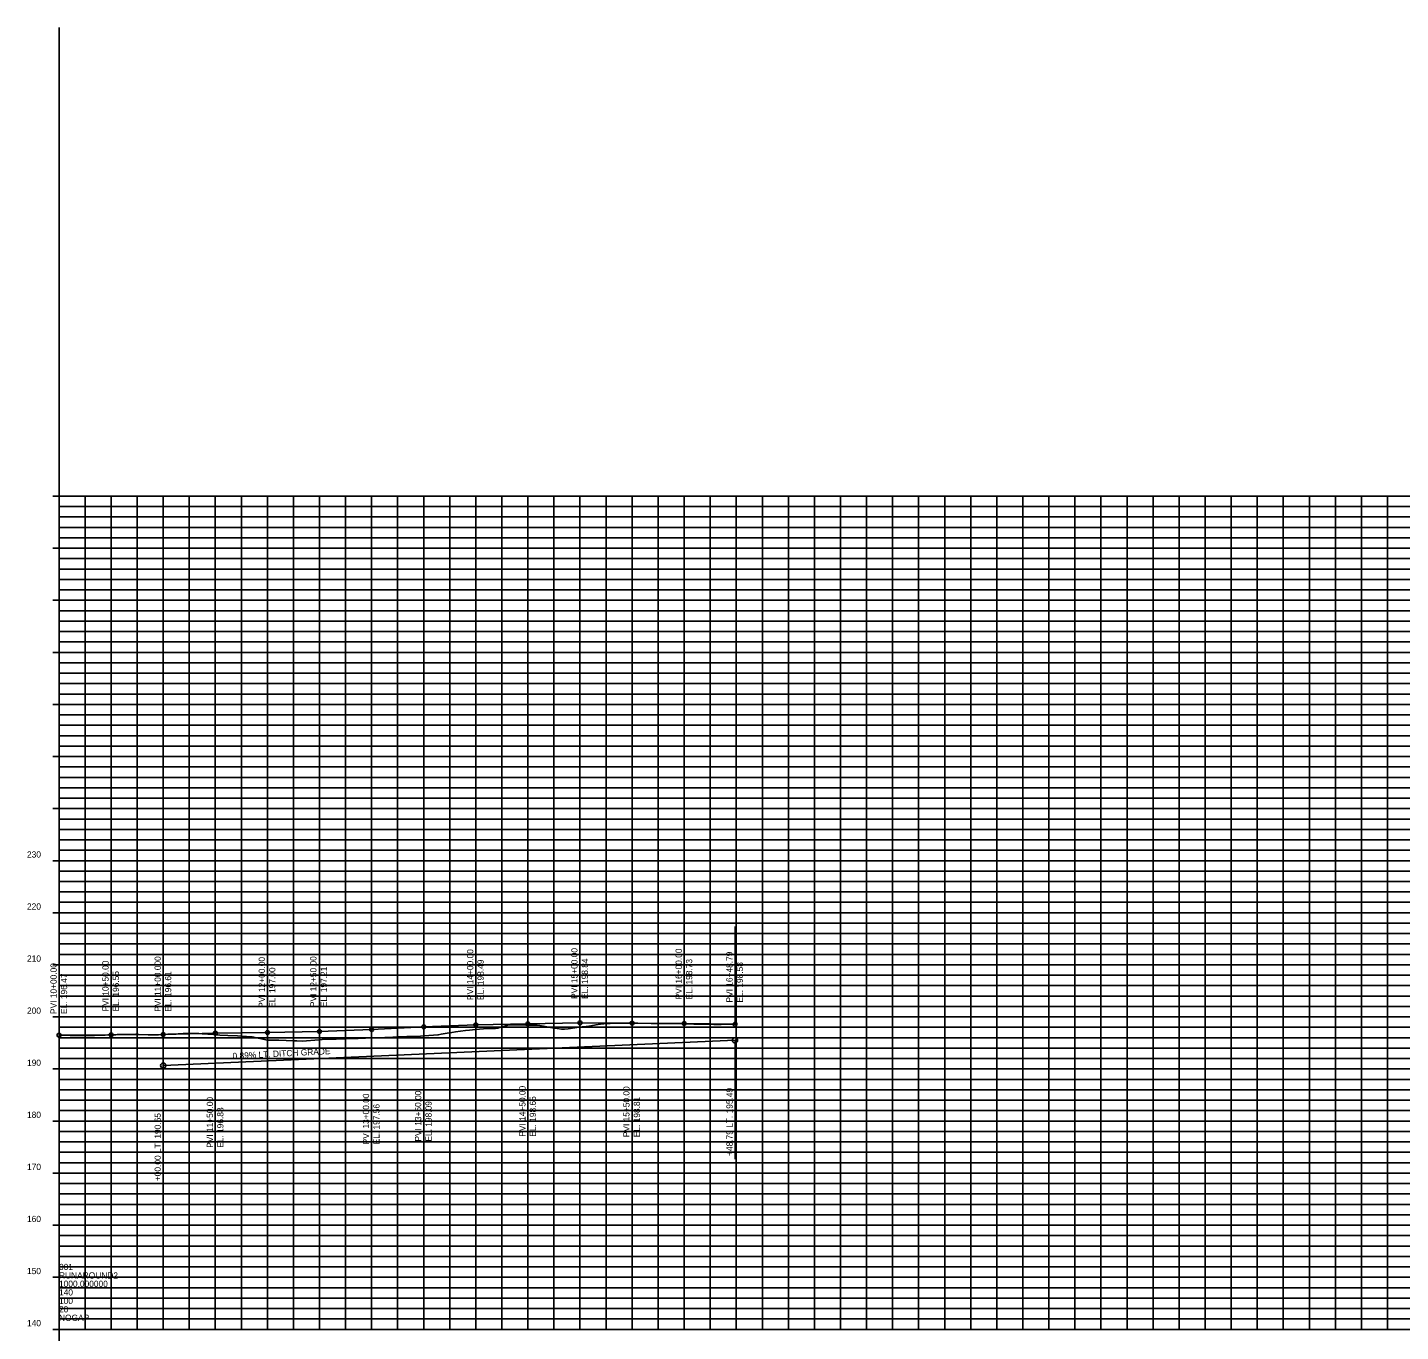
# Model space of a CAD drawing. Extents: x 1384498 to 1391279, y 1965973 to 1976560.
# Drawn here: x 1388219 to 1389536, y 1967221 to 1968473 of the extents above; entities that cross this region are included whole.
import ezdxf

# ---------------------------------------------------------------- set-up
doc = ezdxf.new("R2010")
doc.units = 0
for name, color, linetype in [('63', 7, 'Continuous'), ('Default', 7, 'Continuous'), ('R_Axis_Annotation', 7, 'Continuous'), ('R_Exist Surface', 7, 'Continuous'), ('R_Grid', 7, 'Continuous'), ('R_Grid Annot', 7, 'Continuous'), ('R_Grid_Minor', 7, 'Continuous'), ('R_Vert Alg', 7, 'Continuous'), ('R_Vert Alg Annot', 7, 'Continuous')]:
    doc.layers.add(name, color=color, linetype=linetype)

msp = doc.modelspace()

# ---------------------------------------------------------------- linework, layer by layer
at = {"layer": 'Default'}
for q in [(1388248.8, 1968473.1), (1388948.8, 1967223.1), (1388248.8, 1965973.1)]:
    msp.add_line((1388248.8, 1967223.1), q, dxfattribs=at)
at = {"layer": 'R_Exist Surface'}
for points in [[(1388248.8, 1967505.5), (1388259.6, 1967505.3), (1388259.7, 1967505.3), (1388263, 1967505.2), (1388270.6, 1967505.1), (1388270.6, 1967505.1), (1388278, 1967505.2), (1388281.6, 1967505.3), (1388282.8, 1967505.3), (1388292.5, 1967505.6), (1388293, 1967505.7), (1388295.7, 1967505.8), (1388298.3, 1967505.8), (1388303.1, 1967506), (1388303.4, 1967506), (1388304.6, 1967506.1), (1388308, 1967506.2), (1388314.4, 1967506.3), (1388322.4, 1967506.4), (1388323.1, 1967506.4), (1388325.3, 1967506.3), (1388334.4, 1967505.9), (1388336.2, 1967505.9), (1388338, 1967505.9), (1388344.2, 1967505.9), (1388347.2, 1967506.1), (1388353.1, 1967506.4), (1388357.7, 1967506.5), (1388358.1, 1967506.6), (1388368, 1967507), (1388368.6, 1967507), (1388369, 1967507), (1388369.8, 1967507), (1388380, 1967507.1), (1388382.9, 1967507), (1388386.1, 1967506.7), (1388397.2, 1967506.1), (1388403.2, 1967505.7), (1388410.9, 1967505.3), (1388420, 1967504.8), (1388423.7, 1967504.7), (1388433.9, 1967504), (1388435.7, 1967503.6), (1388437.1, 1967503.3), (1388449, 1967500.9), (1388459.7, 1967500.6), (1388473.7, 1967500.1), (1388476.9, 1967500), (1388482.6, 1967499.8), (1388498, 1967501.2), (1388501.3, 1967501.4), (1388510.6, 1967501.6), (1388514.7, 1967501.8), (1388523.3, 1967502), (1388528.4, 1967502.2), (1388536, 1967502.5), (1388542.9, 1967502.7), (1388548.7, 1967502.9), (1388555.6, 1967503.1), (1388561.4, 1967503.4), (1388569.2, 1967503.6), (1388574.2, 1967503.9), (1388582.5, 1967504.2), (1388586.8, 1967504.4), (1388595.7, 1967504.6), (1388599.5, 1967504.8), (1388612.3, 1967505.8), (1388612.4, 1967505.8), (1388612.8, 1967505.8), (1388615.7, 1967506.4), (1388623.1, 1967507.7), (1388625.7, 1967508.1), (1388629.3, 1967508.7), (1388634.2, 1967509.4), (1388639, 1967509.9), (1388642.8, 1967510.5), (1388645.7, 1967510.8), (1388652.2, 1967511.3), (1388656.3, 1967511.6), (1388667.6, 1967512.1), (1388669.1, 1967512.2), (1388669.8, 1967512.4), (1388670.7, 1967512.6), (1388678.5, 1967514.9), (1388680.2, 1967515.6), (1388683.1, 1967515.5), (1388683.4, 1967515.5), (1388694.1, 1967515.4), (1388696.9, 1967515.3), (1388700.2, 1967515.3), (1388707.5, 1967515.2), (1388710.4, 1967514.7), (1388723.9, 1967512.4), (1388726.8, 1967512), (1388731, 1967511.3), (1388732.3, 1967511.2), (1388734, 1967511.2), (1388737.5, 1967511.7), (1388748, 1967513.3), (1388751, 1967513.6), (1388754.8, 1967513.9)], [(1388754.8, 1967513.9), (1388755.4, 1967514), (1388762.7, 1967515.3), (1388764.3, 1967515.6), (1388770.4, 1967516.4), (1388771.6, 1967516.6), (1388773.8, 1967516.8), (1388777.6, 1967516.9), (1388780.1, 1967517), (1388786.2, 1967517.2), (1388786.7, 1967517.2), (1388789.3, 1967517.2), (1388791, 1967517.2), (1388801.9, 1967517.2), (1388803.7, 1967517.2), (1388804.3, 1967517.2), (1388817, 1967516.8), (1388817.6, 1967516.8), (1388823.7, 1967516.8), (1388826.2, 1967516.8), (1388830.9, 1967516.9), (1388831.8, 1967516.9), (1388832.1, 1967516.9), (1388842.4, 1967516.9), (1388844.3, 1967516.9), (1388847.2, 1967516.8), (1388851.4, 1967516.6), (1388855, 1967516.4), (1388857.6, 1967516.3), (1388858.5, 1967516.2), (1388862.2, 1967516.1), (1388867.5, 1967516), (1388870.9, 1967516), (1388877.2, 1967515.9), (1388884.2, 1967515.9), (1388891.4, 1967516), (1388892.2, 1967516), (1388896.6, 1967516), (1388897.6, 1967516)]]:
    msp.add_lwpolyline(points, dxfattribs=at)
at = {"layer": 'R_Grid'}
for p, q in [((1388248.8, 1967223.1), (1388248.8, 1968023.1)), ((1388248.8, 1968023.1), (1390848.8, 1968023.1)), ((1388248.8, 1968023.1), (1390848.8, 1968023.1)), ((1388348.8, 1967223.1), (1388348.8, 1968023.1)), ((1388448.8, 1967223.1), (1388448.8, 1968023.1)), ((1388548.8, 1967223.1), (1388548.8, 1968023.1)), ((1388648.8, 1967223.1), (1388648.8, 1968023.1)), ((1388748.8, 1967223.1), (1388748.8, 1968023.1)), ((1388848.8, 1967223.1), (1388848.8, 1968023.1)), ((1388948.8, 1967223.1), (1388948.8, 1968023.1)), ((1389048.8, 1967223.1), (1389048.8, 1968023.1)), ((1389148.8, 1967223.1), (1389148.8, 1968023.1)), ((1389248.8, 1967223.1), (1389248.8, 1968023.1)), ((1389348.8, 1967223.1), (1389348.8, 1968023.1)), ((1389448.8, 1967223.1), (1389448.8, 1968023.1)), ((1388248.8, 1967973.1), (1390848.8, 1967973.1)), ((1388248.8, 1967923.1), (1390848.8, 1967923.1)), ((1388248.8, 1967873.1), (1390848.8, 1967873.1)), ((1388248.8, 1967823.1), (1390848.8, 1967823.1)), ((1388248.8, 1967773.1), (1390848.8, 1967773.1)), ((1388248.8, 1967723.1), (1390848.8, 1967723.1)), ((1388248.8, 1967673.1), (1390848.8, 1967673.1)), ((1388248.8, 1967623.1), (1390848.8, 1967623.1)), ((1388248.8, 1967573.1), (1390848.8, 1967573.1)), ((1388248.8, 1967523.1), (1390848.8, 1967523.1)), ((1388248.8, 1967473.1), (1390848.8, 1967473.1)), ((1388248.8, 1967423.1), (1390848.8, 1967423.1)), ((1388248.8, 1967373.1), (1390848.8, 1967373.1)), ((1388248.8, 1967323.1), (1390848.8, 1967323.1)), ((1388248.8, 1967273.1), (1390848.8, 1967273.1)), ((1388248.8, 1967223.1), (1390848.8, 1967223.1))]:
    msp.add_line(p, q, dxfattribs=at)
at = {"layer": 'R_Grid Annot'}
for p, q in [((1388242.8, 1968023.1), (1388248.8, 1968023.1)), ((1388242.8, 1968023.1), (1388248.8, 1968023.1)), ((1388248.8, 1968013.1), (1388251.8, 1968013.1)), ((1388248.8, 1968003.1), (1388251.8, 1968003.1)), ((1388248.8, 1967993.1), (1388251.8, 1967993.1)), ((1388248.8, 1967983.1), (1388251.8, 1967983.1)), ((1388242.8, 1967973.1), (1388248.8, 1967973.1)), ((1388248.8, 1967963.1), (1388251.8, 1967963.1)), ((1388248.8, 1967953.1), (1388251.8, 1967953.1)), ((1388248.8, 1967943.1), (1388251.8, 1967943.1)), ((1388248.8, 1967933.1), (1388251.8, 1967933.1)), ((1388242.8, 1967923.1), (1388248.8, 1967923.1)), ((1388248.8, 1967913.1), (1388251.8, 1967913.1)), ((1388248.8, 1967903.1), (1388251.8, 1967903.1)), ((1388248.8, 1967893.1), (1388251.8, 1967893.1)), ((1388248.8, 1967883.1), (1388251.8, 1967883.1)), ((1388242.8, 1967873.1), (1388248.8, 1967873.1)), ((1388248.8, 1967863.1), (1388251.8, 1967863.1)), ((1388248.8, 1967853.1), (1388251.8, 1967853.1)), ((1388248.8, 1967843.1), (1388251.8, 1967843.1)), ((1388242.8, 1967823.1), (1388248.8, 1967823.1)), ((1388248.8, 1967833.1), (1388251.8, 1967833.1)), ((1388248.8, 1967813.1), (1388251.8, 1967813.1)), ((1388248.8, 1967803.1), (1388251.8, 1967803.1)), ((1388248.8, 1967793.1), (1388251.8, 1967793.1)), ((1388248.8, 1967783.1), (1388251.8, 1967783.1)), ((1388242.8, 1967773.1), (1388248.8, 1967773.1)), ((1388248.8, 1967763.1), (1388251.8, 1967763.1)), ((1388248.8, 1967753.1), (1388251.8, 1967753.1)), ((1388248.8, 1967743.1), (1388251.8, 1967743.1)), ((1388248.8, 1967733.1), (1388251.8, 1967733.1)), ((1388242.8, 1967723.1), (1388248.8, 1967723.1)), ((1388248.8, 1967713.1), (1388251.8, 1967713.1)), ((1388248.8, 1967703.1), (1388251.8, 1967703.1)), ((1388248.8, 1967693.1), (1388251.8, 1967693.1)), ((1388248.8, 1967683.1), (1388251.8, 1967683.1)), ((1388242.8, 1967673.1), (1388248.8, 1967673.1)), ((1388248.8, 1967663.1), (1388251.8, 1967663.1)), ((1388248.8, 1967653.1), (1388251.8, 1967653.1)), ((1388248.8, 1967643.1), (1388251.8, 1967643.1)), ((1388248.8, 1967633.1), (1388251.8, 1967633.1)), ((1388242.8, 1967623.1), (1388248.8, 1967623.1)), ((1388248.8, 1967613.1), (1388251.8, 1967613.1)), ((1388248.8, 1967603.1), (1388251.8, 1967603.1)), ((1388248.8, 1967593.1), (1388251.8, 1967593.1)), ((1388242.8, 1967573.1), (1388248.8, 1967573.1)), ((1388248.8, 1967583.1), (1388251.8, 1967583.1)), ((1388248.8, 1967563.1), (1388251.8, 1967563.1)), ((1388248.8, 1967553.1), (1388251.8, 1967553.1)), ((1388248.8, 1967543.1), (1388251.8, 1967543.1)), ((1388248.8, 1967533.1), (1388251.8, 1967533.1)), ((1388242.8, 1967523.1), (1388248.8, 1967523.1)), ((1388248.8, 1967513.1), (1388251.8, 1967513.1)), ((1388248.8, 1967503.1), (1388251.8, 1967503.1)), ((1388248.8, 1967493.1), (1388251.8, 1967493.1)), ((1388248.8, 1967483.1), (1388251.8, 1967483.1)), ((1388242.8, 1967473.1), (1388248.8, 1967473.1)), ((1388248.8, 1967463.1), (1388251.8, 1967463.1)), ((1388248.8, 1967453.1), (1388251.8, 1967453.1)), ((1388248.8, 1967443.1), (1388251.8, 1967443.1)), ((1388248.8, 1967433.1), (1388251.8, 1967433.1)), ((1388242.8, 1967423.1), (1388248.8, 1967423.1)), ((1388248.8, 1967413.1), (1388251.8, 1967413.1)), ((1388248.8, 1967403.1), (1388251.8, 1967403.1)), ((1388248.8, 1967393.1), (1388251.8, 1967393.1)), ((1388248.8, 1967383.1), (1388251.8, 1967383.1)), ((1388242.8, 1967373.1), (1388248.8, 1967373.1)), ((1388248.8, 1967363.1), (1388251.8, 1967363.1)), ((1388248.8, 1967353.1), (1388251.8, 1967353.1)), ((1388248.8, 1967343.1), (1388251.8, 1967343.1)), ((1388242.8, 1967323.1), (1388248.8, 1967323.1)), ((1388248.8, 1967333.1), (1388251.8, 1967333.1)), ((1388248.8, 1967313.1), (1388251.8, 1967313.1)), ((1388248.8, 1967303.1), (1388251.8, 1967303.1)), ((1388248.8, 1967293.1), (1388251.8, 1967293.1)), ((1388248.8, 1967283.1), (1388251.8, 1967283.1)), ((1388242.8, 1967273.1), (1388248.8, 1967273.1)), ((1388248.8, 1967263.1), (1388251.8, 1967263.1)), ((1388248.8, 1967253.1), (1388251.8, 1967253.1)), ((1388248.8, 1967243.1), (1388251.8, 1967243.1)), ((1388248.8, 1967233.1), (1388251.8, 1967233.1)), ((1388242.8, 1967223.1), (1388248.8, 1967223.1))]:
    msp.add_line(p, q, dxfattribs=at)
at = {"layer": 'R_Grid_Minor'}
for p, q in [((1388273.8, 1967223.1), (1388273.8, 1968023.1)), ((1388298.8, 1967223.1), (1388298.8, 1968023.1)), ((1388323.8, 1967223.1), (1388323.8, 1968023.1)), ((1388373.8, 1967223.1), (1388373.8, 1968023.1)), ((1388398.8, 1967223.1), (1388398.8, 1968023.1)), ((1388423.8, 1967223.1), (1388423.8, 1968023.1)), ((1388473.8, 1967223.1), (1388473.8, 1968023.1)), ((1388498.8, 1967223.1), (1388498.8, 1968023.1)), ((1388523.8, 1967223.1), (1388523.8, 1968023.1)), ((1388573.8, 1967223.1), (1388573.8, 1968023.1)), ((1388598.8, 1967223.1), (1388598.8, 1968023.1)), ((1388623.8, 1967223.1), (1388623.8, 1968023.1)), ((1388673.8, 1967223.1), (1388673.8, 1968023.1)), ((1388698.8, 1967223.1), (1388698.8, 1968023.1)), ((1388723.8, 1967223.1), (1388723.8, 1968023.1)), ((1388773.8, 1967223.1), (1388773.8, 1968023.1)), ((1388798.8, 1967223.1), (1388798.8, 1968023.1)), ((1388823.8, 1967223.1), (1388823.8, 1968023.1)), ((1388873.8, 1967223.1), (1388873.8, 1968023.1)), ((1388898.8, 1967223.1), (1388898.8, 1968023.1)), ((1388923.8, 1967223.1), (1388923.8, 1968023.1)), ((1388973.8, 1967223.1), (1388973.8, 1968023.1)), ((1388998.8, 1967223.1), (1388998.8, 1968023.1)), ((1389023.8, 1967223.1), (1389023.8, 1968023.1)), ((1389073.8, 1967223.1), (1389073.8, 1968023.1)), ((1389098.8, 1967223.1), (1389098.8, 1968023.1)), ((1389123.8, 1967223.1), (1389123.8, 1968023.1)), ((1389173.8, 1967223.1), (1389173.8, 1968023.1)), ((1389198.8, 1967223.1), (1389198.8, 1968023.1)), ((1389223.8, 1967223.1), (1389223.8, 1968023.1)), ((1389273.8, 1967223.1), (1389273.8, 1968023.1)), ((1389298.8, 1967223.1), (1389298.8, 1968023.1)), ((1389323.8, 1967223.1), (1389323.8, 1968023.1)), ((1389373.8, 1967223.1), (1389373.8, 1968023.1)), ((1389398.8, 1967223.1), (1389398.8, 1968023.1)), ((1389423.8, 1967223.1), (1389423.8, 1968023.1)), ((1389473.8, 1967223.1), (1389473.8, 1968023.1)), ((1389498.8, 1967223.1), (1389498.8, 1968023.1)), ((1389523.8, 1967223.1), (1389523.8, 1968023.1)), ((1388248.8, 1968013.1), (1390848.8, 1968013.1)), ((1388248.8, 1968003.1), (1390848.8, 1968003.1)), ((1388248.8, 1967993.1), (1390848.8, 1967993.1)), ((1388248.8, 1967983.1), (1390848.8, 1967983.1)), ((1388248.8, 1967963.1), (1390848.8, 1967963.1)), ((1388248.8, 1967953.1), (1390848.8, 1967953.1)), ((1388248.8, 1967943.1), (1390848.8, 1967943.1)), ((1388248.8, 1967933.1), (1390848.8, 1967933.1)), ((1388248.8, 1967913.1), (1390848.8, 1967913.1)), ((1388248.8, 1967903.1), (1390848.8, 1967903.1)), ((1388248.8, 1967893.1), (1390848.8, 1967893.1)), ((1388248.8, 1967883.1), (1390848.8, 1967883.1)), ((1388248.8, 1967863.1), (1390848.8, 1967863.1)), ((1388248.8, 1967853.1), (1390848.8, 1967853.1)), ((1388248.8, 1967843.1), (1390848.8, 1967843.1)), ((1388248.8, 1967833.1), (1390848.8, 1967833.1)), ((1388248.8, 1967813.1), (1390848.8, 1967813.1)), ((1388248.8, 1967803.1), (1390848.8, 1967803.1)), ((1388248.8, 1967793.1), (1390848.8, 1967793.1)), ((1388248.8, 1967783.1), (1390848.8, 1967783.1)), ((1388248.8, 1967763.1), (1390848.8, 1967763.1)), ((1388248.8, 1967753.1), (1390848.8, 1967753.1)), ((1388248.8, 1967743.1), (1390848.8, 1967743.1)), ((1388248.8, 1967733.1), (1390848.8, 1967733.1)), ((1388248.8, 1967713.1), (1390848.8, 1967713.1)), ((1388248.8, 1967703.1), (1390848.8, 1967703.1)), ((1388248.8, 1967693.1), (1390848.8, 1967693.1)), ((1388248.8, 1967683.1), (1390848.8, 1967683.1)), ((1388248.8, 1967663.1), (1390848.8, 1967663.1)), ((1388248.8, 1967653.1), (1390848.8, 1967653.1)), ((1388248.8, 1967643.1), (1390848.8, 1967643.1)), ((1388248.8, 1967633.1), (1390848.8, 1967633.1)), ((1388248.8, 1967613.1), (1390848.8, 1967613.1)), ((1388248.8, 1967603.1), (1390848.8, 1967603.1)), ((1388248.8, 1967593.1), (1390848.8, 1967593.1)), ((1388248.8, 1967583.1), (1390848.8, 1967583.1)), ((1388248.8, 1967563.1), (1390848.8, 1967563.1)), ((1388248.8, 1967553.1), (1390848.8, 1967553.1)), ((1388248.8, 1967543.1), (1390848.8, 1967543.1)), ((1388248.8, 1967533.1), (1390848.8, 1967533.1)), ((1388248.8, 1967513.1), (1390848.8, 1967513.1)), ((1388248.8, 1967503.1), (1390848.8, 1967503.1)), ((1388248.8, 1967493.1), (1390848.8, 1967493.1)), ((1388248.8, 1967483.1), (1390848.8, 1967483.1)), ((1388248.8, 1967463.1), (1390848.8, 1967463.1)), ((1388248.8, 1967453.1), (1390848.8, 1967453.1)), ((1388248.8, 1967443.1), (1390848.8, 1967443.1)), ((1388248.8, 1967433.1), (1390848.8, 1967433.1)), ((1388248.8, 1967413.1), (1390848.8, 1967413.1)), ((1388248.8, 1967403.1), (1390848.8, 1967403.1)), ((1388248.8, 1967393.1), (1390848.8, 1967393.1)), ((1388248.8, 1967383.1), (1390848.8, 1967383.1)), ((1388248.8, 1967363.1), (1390848.8, 1967363.1)), ((1388248.8, 1967353.1), (1390848.8, 1967353.1)), ((1388248.8, 1967343.1), (1390848.8, 1967343.1)), ((1388248.8, 1967333.1), (1390848.8, 1967333.1)), ((1388248.8, 1967313.1), (1390848.8, 1967313.1)), ((1388248.8, 1967303.1), (1390848.8, 1967303.1)), ((1388248.8, 1967293.1), (1390848.8, 1967293.1)), ((1388248.8, 1967283.1), (1390848.8, 1967283.1)), ((1388248.8, 1967263.1), (1390848.8, 1967263.1)), ((1388248.8, 1967253.1), (1390848.8, 1967253.1)), ((1388248.8, 1967243.1), (1390848.8, 1967243.1)), ((1388248.8, 1967233.1), (1390848.8, 1967233.1))]:
    msp.add_line(p, q, dxfattribs=at)
at = {"layer": 'R_Vert Alg'}
msp.add_line((1388348.8, 1967476.4), (1388897.6, 1967500.6), dxfattribs=at)
msp.add_lwpolyline([(1388248.8, 1967505.5), (1388298.8, 1967505.9), (1388348.8, 1967506.2), (1388398.8, 1967507.5), (1388448.8, 1967508.1), (1388498.8, 1967509.2), (1388548.8, 1967510.9), (1388598.8, 1967513.6), (1388648.8, 1967515.6), (1388698.8, 1967516.4), (1388748.8, 1967517.3), (1388798.8, 1967517.2), (1388848.8, 1967516.8), (1388897.6, 1967516)], dxfattribs=at)
at = {"layer": 'R_Vert Alg Annot'}
for p, q in [((1388748.8, 1967527.3), (1388748.8, 1967611.3)), ((1388248.8, 1967515.5), (1388248.8, 1967599.5)), ((1388298.8, 1967515.9), (1388298.8, 1967599.9)), ((1388348.8, 1967600.2), (1388348.8, 1967590.2)), ((1388448.8, 1967518.1), (1388448.8, 1967602.1)), ((1388498.8, 1967519.2), (1388498.8, 1967603.2)), ((1388648.8, 1967525.6), (1388648.8, 1967609.6)), ((1388848.8, 1967526.8), (1388848.8, 1967610.8)), ((1388897.6, 1967610), (1388897.6, 1967600)), ((1388897.6, 1967600), (1388897.6, 1967516)), ((1388348.8, 1967590.2), (1388348.8, 1967506.2)), ((1388498.8, 1967509.2), (1388498.8, 1967519.2)), ((1388648.8, 1967515.6), (1388648.8, 1967525.6)), ((1388748.8, 1967517.3), (1388748.8, 1967527.3)), ((1388848.8, 1967516.8), (1388848.8, 1967526.8)), ((1388248.8, 1967505.5), (1388248.8, 1967515.5)), ((1388298.8, 1967505.9), (1388298.8, 1967515.9)), ((1388398.8, 1967507.5), (1388398.8, 1967497.5)), ((1388448.8, 1967508.1), (1388448.8, 1967518.1)), ((1388548.8, 1967510.9), (1388548.8, 1967500.9)), ((1388598.8, 1967513.6), (1388598.8, 1967503.6)), ((1388698.8, 1967516.4), (1388698.8, 1967506.4)), ((1388698.8, 1967506.4), (1388698.8, 1967405.3)), ((1388798.8, 1967517.2), (1388798.8, 1967507.2)), ((1388798.8, 1967507.2), (1388798.8, 1967404.8)), ((1388398.8, 1967497.5), (1388398.8, 1967395.7)), ((1388548.8, 1967500.9), (1388548.8, 1967398.5)), ((1388598.8, 1967503.6), (1388598.8, 1967400.1)), ((1388897.6, 1967500.6), (1388897.6, 1967470.6)), ((1388348.8, 1967476.4), (1388348.8, 1967446.4)), ((1388897.6, 1967470.6), (1388897.6, 1967386.6)), ((1388348.8, 1967446.4), (1388348.8, 1967362.4))]:
    msp.add_line(p, q, dxfattribs=at)
for centre, radius in [((1388748.8, 1967517.3), 1.85), ((1388798.8, 1967517.2), 1.85), ((1388248.8, 1967505.5), 1.85), ((1388298.8, 1967505.9), 1.85), ((1388348.8, 1967506.2), 1.85), ((1388398.8, 1967507.5), 1.85), ((1388448.8, 1967508.1), 1.85), ((1388498.8, 1967509.2), 1.85), ((1388548.8, 1967510.9), 1.85), ((1388598.8, 1967513.6), 1.85), ((1388648.8, 1967515.6), 1.85), ((1388698.8, 1967516.4), 1.85), ((1388848.8, 1967516.8), 1.85), ((1388897.6, 1967516), 1.85), ((1388897.6, 1967500.6), 2.5), ((1388348.8, 1967476.4), 2.5)]:
    msp.add_circle(centre, radius, dxfattribs=at)

# ---------------------------------------------------------------- texts
at = {"layer": '63'}
msp.add_text('-', height=0.0001, dxfattribs=at).set_placement((1388248.8, 1967223.1))
at = {"layer": 'Default'}
for s, p in [('001', (1388248.8, 1967280)), ('RUNAROUND2', (1388248.8, 1967271.9)), ('1000.000000', (1388248.8, 1967263.8)), ('140', (1388248.8, 1967255.6)), ('20', (1388248.8, 1967239.4)), ('100', (1388248.8, 1967247.5)), ('NOGAP', (1388248.8, 1967231.2))]:
    msp.add_text(s, height=6, dxfattribs=at).set_placement(p)
at = {"layer": 'R_Axis_Annotation'}
for s, p in [('230', (1388218.1, 1967676.1)), ('220', (1388218.1, 1967626.1)), ('210', (1388218.1, 1967576.1)), ('200', (1388218.1, 1967526.1)), ('190', (1388218.1, 1967476.1)), ('180', (1388218.1, 1967426.1)), ('170', (1388218.1, 1967376.1)), ('160', (1388218.1, 1967326.1)), ('150', (1388218.1, 1967276.1)), ('140', (1388218.1, 1967226.1))]:
    msp.add_text(s, height=6, dxfattribs=at).set_placement(p)
at = {"layer": 'R_Vert Alg Annot'}
for s, rotation, p in [('PVI 14+00.00', 90, (1388646.4, 1967539.3)), ('PVI 15+00.00', 90, (1388746.4, 1967540.4)), ('PVI 16+00.00', 90, (1388846.5, 1967539.9)), ('PVI 16+48.79', 90, (1388895.2, 1967536.9)), ('PVI 10+00.00', 90, (1388246.6, 1967525.9)), ('PVI 10+50.00', 90, (1388296.4, 1967528.3)), ('PVI 11+00.000', 90, (1388346.5, 1967528)), ('PVI 12+00.00', 90, (1388446.4, 1967531.8)), ('PVI 12+50.00', 90, (1388495.9, 1967532.5)), ('EL. 198.49', 90, (1388656.4, 1967539.3)), ('EL. 198.84', 90, (1388756.4, 1967540.4)), ('EL. 198.73', 90, (1388856.5, 1967539.9)), ('EL. 198.58', 90, (1388905.2, 1967536.9)), ('EL. 196.47', 90, (1388256.6, 1967525.9)), ('EL. 196.55', 90, (1388306.4, 1967528.3)), ('EL. 196.61', 90, (1388356.5, 1967528)), ('EL. 197.00', 90, (1388456.4, 1967531.8)), ('EL. 197.21', 90, (1388505.9, 1967532.5)), ('0.89% LT. DITCH GRADE', 2.9859, (1388415.5, 1967482.5)), ('PVI 14+50.00', 90, (1388696.5, 1967408.1)), ('PVI 15+50.00', 90, (1388796.3, 1967407.6)), ('+48.79 LT. 195.49', 90, (1388895.3, 1967389.6)), ('PVI 11+50.00', 90, (1388396.6, 1967397.4)), ('PVI 13+00.00', 90, (1388546.4, 1967400.7)), ('PVI 13+50.00', 90, (1388596.4, 1967403.4)), ('EL. 198.09', 90, (1388606.4, 1967403.4)), ('EL. 198.65', 90, (1388706.5, 1967408.1)), ('EL. 198.81', 90, (1388806.3, 1967407.6)), ('+00.00 LT. 190.65', 90, (1388346.5, 1967365.4)), ('EL. 196.88', 90, (1388406.6, 1967397.4)), ('EL. 197.56', 90, (1388556.4, 1967400.7))]:
    msp.add_text(s, height=6, rotation=rotation, dxfattribs=at).set_placement(p)

doc.saveas('drawing.dxf')
